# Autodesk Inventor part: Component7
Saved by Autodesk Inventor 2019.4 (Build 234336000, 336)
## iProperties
Created: 2020-06
Part Number: Component7
Material: Generic
Document SubType Name: Modeling
Designer: Administrator
Density: 1 g/cm^3
Appearance: Default
Title: Component7
Author: Administrator
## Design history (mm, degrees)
